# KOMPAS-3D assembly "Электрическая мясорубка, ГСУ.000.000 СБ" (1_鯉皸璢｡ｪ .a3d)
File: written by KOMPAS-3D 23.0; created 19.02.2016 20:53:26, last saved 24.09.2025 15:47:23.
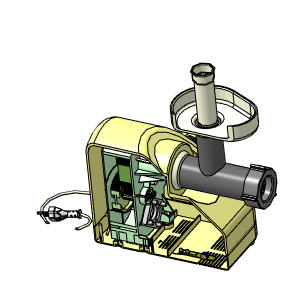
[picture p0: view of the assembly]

Document properties: Автор: Аня; Полное имя файла: C:\Users\zyrianova_ae\Desktop\Задание_колледж\Модели\Сборка мясорубки.a3d

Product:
- Component [detail]: Основание корпуса  | pos. 1  | Материал: Фторопласт-4  ГОСТ 10007-80 Е (density 2200 kg/m3); Масса: 0.272568; Автор: Аня; source file: Основание корпуса.m3d
- Component [detail]: Амортизатор  | pos. 10  | Масса: 0.016894; Автор: Аня; source file: Амортизатор (4 шт).m3d
- Component [detail]: Амортизатор  | pos. 11  | Масса: 0.016894; Автор: Аня; source file: Амортизатор (4 шт).m3d
- Component [detail]: Амортизатор  | pos. 12  | Масса: 0.016894; Автор: Аня; source file: Амортизатор (4 шт).m3d
- Component [detail]: Амортизатор  | pos. 13  | Масса: 0.016894; Автор: Аня; source file: Амортизатор (4 шт).m3d
- Component [detail]: Подушечка  | pos. 14  | Масса: 0.003215; Автор: Аня; source file: Подушечка .m3d
- Component [detail]: Подушечка  | pos. 15  | Масса: 0.003215; Автор: Аня; source file: Подушечка .m3d
- Component [detail]: Подушечка  | pos. 16  | Масса: 0.003215; Автор: Аня; source file: Подушечка .m3d
- Component [detail]: Подушечка  | pos. 17  | Масса: 0.003215; Автор: Аня; source file: Подушечка .m3d
- Component [detail]: Подушечка  | pos. 18  | Масса: 0.003215; Автор: Аня; source file: Подушечка .m3d
- Component [detail]: Подушечка  | pos. 19  | Масса: 0.003215; Автор: Аня; source file: Подушечка .m3d
- Component [detail]: Подушечка  | pos. 20  | Масса: 0.003215; Автор: Аня; source file: Подушечка .m3d
- Component [detail]: Подушечка  | pos. 21  | Масса: 0.003215; Автор: Аня; source file: Подушечка .m3d
- Component [assembly]: Редуктор  | pos. 2  | Масса: 3.0172; Автор: Аня; source file: Сборка редуктора.a3d
- Component [assembly]: Выключатель  | pos. 4  | Масса: 0.033755; Автор: Аня; source file: Выключатель.a3d
- Component [detail]: Плата  | pos. 5  | Масса: 0.019638; Автор: Аня; source file: Плата.m3d
- Component [assembly]: Сборка внешних деталей мясорубки  | pos. 6  | Масса: 5.888839; Автор: Аня; source file: Вторая сборка.a3d
- Component [detail]: Стопорный болт  | pos. 7  | Масса: 0.088582; Автор: Аня; source file: Стопорный болт.m3d
- Component [detail]: Вилка  | pos. 8  | Масса: 0.091381; Автор: Аня; source file: Вилка.m3d
- Component [detail]: Держатель провода  | pos. 9  | Масса: 0.003792; Автор: Аня; source file: Держатель провода.m3d
- Body: Тело 3
    Масса: 0.039235
- Component [standard]: Шайба A 4 ГОСТ 6958-78  | qty 4  | Масса: 0.000774; Раздел спецификации: Стандартные изделия; Рассекать на разрезах: no
- Component [standard]: Шуруп 1-4x20.019 ГОСТ 1144-80  | qty 4  | pos. 36  | Материал: Сталь 08кп ГОСТ 1050-2013 (density 7871 kg/m3); Масса: 0.00198; Раздел спецификации: Стандартные изделия; Рассекать на разрезах: no; additional columns: BOSimple***Material:aed9f2af-caf6-4059-826c-b94d4af93e47
- Part/product: Электрическая мясорубка  | designation ГСУ.000.000 СБ
    Масса: 9.559299

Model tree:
1. Сечение поверхностью:1
2. Смещенная плоскость:1
     Расстояние = 15
3. Смещенная плоскость:2
     Расстояние = 63
4. Эскиз:1
5. Эскиз:3  (with: Операция выдавливания:2)
6. Эскиз:4  (with: Операция выдавливания:6)
7. Эскиз:6  (with: Операция выдавливания:2, Вырезать элемент выдавливания:14)
8. Эскиз:7  (with: Вырезать элемент выдавливания:1, Вырезать элемент выдавливания:2)
9. Смещенная плоскость:3  (with: Операция выдавливания:2)
     Расстояние = 12
10. Эскиз:8  (with: Операция выдавливания:1)
11. Эскиз:9  (with: Операция выдавливания:6, Вырезать элемент выдавливания:14)
12. Эскиз:10  (with: Операция выдавливания:2, Вырезать элемент выдавливания:14)
13. Эскиз:11  (with: Операция выдавливания:2)
14. Эскиз:12  (with: Операция выдавливания:7)
15. Эскиз:13  (with: Операция выдавливания:1, Вырезать элемент выдавливания:20)
16. Сплайн:4
     Координата X = 24.0569; Координата Y = 47.5876; Координата Z = 4.9171; Координата X = -2.76426; Координата Y = 55.0577; Координата Z = 3.36768; Координата X = -16.3145; Координата Y = 63.0116; Координата Z = 3; Координата X = -38.7823; Координата Y = 63; Координата Z = 2.99512; Координата X = -61.2823; Координата Y = 63; Координата Z = 2.99512; Координата X = -82; Координата Y = 30.4165; Координата Z = -3.17361; Координата X = -100; Координата Z = -10; Координата X = -102; Координата Z = -10; Координата X = -120.657; Координата Y = -31.7341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
17. Кинематическая операция:3
18. Эскиз:14  (with: Кинематическая операция:3)
19. Эскиз:15  (with: Операция выдавливания:2)
20. Смещенная плоскость:5  (with: Вырезать элемент выдавливания:1)
     Расстояние = 3
21. Эскиз:16
22. Эскиз:17  (with: Кинематическая операция:3)
23. Смещенная плоскость:6  (with: Операция выдавливания:1)
     Расстояние = 2
24. Эскиз:20
25. Сплайн:7
     Координата X = 24.0569; Координата Y = 46.8619; Координата Z = 4.87679; Координата X = 24.0569; Координата Y = 38.923; Координата Z = -0.744157; Координата X = 9.1117; Координата Y = 32; Координата Z = -6.60744; Порядок = 4
26. Кинематическая операция:7
27. Эскиз:21  (with: Операция выдавливания:1)
28. Эскиз:22  (with: Кинематическая операция:3)
29. Смещенная плоскость:7  (with: Операция выдавливания:2)
     Расстояние = 2
30. Смещенная плоскость:8  (with: Вырезать элемент выдавливания:1)
     Расстояние = 7
31. Эскиз:24
32. Эскиз:26
33. Сплайн:9
     Координата X = 24.0569; Координата Y = 48.3019; Координата Z = 4.84943; Координата X = 34.1389; Координата Y = 35.7895; Координата Z = 8; Координата X = 50.0249; Координата Y = 30.353; Координата Z = 8; Координата X = 53.724; Координата Y = 30.4898; Координата Z = 4; Координата X = 46.724; Координата Y = 30.4898; Координата Z = 4; Порядок = 4
34. Эскиз:27  (with: Кинематическая операция:3)
35. Кинематическая операция:9
36. Смещенная плоскость:9  (with: Операция выдавливания:1)
     Расстояние = 2
37. Эскиз:28  (with: Вырезать элемент выдавливания:1)
38. Эскиз:30  (with: Операция выдавливания:1)
39. Эскиз:33  (with: Операция выдавливания:1)
40. Смещенная плоскость:10  (with: Вырезать элемент выдавливания:1)
     Расстояние = 5
41. Эскиз:34
42. Смещенная плоскость:11  (with: Вырезать элемент выдавливания:1)
     Расстояние = 6
43. Эскиз:35  (with: Вырезать элемент выдавливания:1)
44. Смещенная плоскость:12  (with: Операция выдавливания:2)
     Расстояние = 6
45. Эскиз:36  (with: Скругление:1)
46. Смещенная плоскость:13  (with: Вырезать элемент выдавливания:1)
     Расстояние = 6
47. Эскиз:39  (with: Вырезать элемент выдавливания:1, Скругление:5)
48. Эскиз:40  (with: Операция выдавливания:1)
49. Смещенная плоскость:15  (with: Операция выдавливания:1)
     Расстояние = 32
50. Смещенная плоскость:16  (with: Вырезать элемент выдавливания:1)
     Расстояние = 41
51. Смещенная плоскость:24  (with: Операция выдавливания:1)
     Расстояние = 1.5
52. Эскиз:60
53. Эскиз:67
54. Смещенная плоскость:26  (with: Операция выдавливания:1)
     Расстояние = 2
55. Эскиз:68
56. Эскиз:69  (with: Операция выдавливания:1)
57. Эскиз:72  (with: Операция выдавливания:1, Вырезать элемент выдавливания:1)
     Расстояние = 1.3; Ориентация = 2; Расстояние = 2

Referenced files in C:\Users\zyrianova_ae\Desktop\Задание_колледж\Модели\: основание корпуса.m3d, Амортизатор (4 шт).m3d, Подушечка .m3d, Сборка редуктора.a3d, Выключатель.a3d, Плата.m3d, Вторая сборка.a3d, Стопорный болт.m3d, Вилка.m3d, Держатель провода.m3d
Referenced files in C:\DB\SI\Methods\Kompas\3D\: PLib_Washer_1_712.m3d, PLib_Screw_Shurup_900.m3d
Referenced files in T:\ОИТОД\Электрическая мясорубка\Электрическая мясорубка\: Амортизатор (4 шт).m3d, Подушечка .m3d
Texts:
  Крепежное изделие ГОСТ
  BOSimple***PART:9cab8f69-1b85-68b4-05a8-15578942df64***SHORTLOC:Root±140±10±10±60±10±20[Нет;Без покрытия;Без указания материала;-;4]
  BOSimple***PART:990cabac-cbed-c4a6-76a4-a34520e752f7***SHORTLOC:A86A9_907A25C3CFA14727[9;Цинковое, хроматированное;4;20;Сталь 08кп ГОСТ 1050-2013]
  BOSimple***Material:aed9f2af-caf6-4059-826c-b94d4af93e47
  ГСУ.000.000 СБ
  Точка начала. Х
  Точка начала. Y
  Точка начала. Z
  Амортизатор (1)
  Амортизатор (2)
  Амортизатор (3)
  Амортизатор (4)
  Подушечка (1)
  Подушечка (2)
  Подушечка (3)
  Подушечка (4)
  Подушечка (5)
  Подушечка (6)
  Подушечка (7)
  Подушечка (8)
  Шайба A 4 ГОСТ 6958-78 (1)
  Шайба A 4 ГОСТ 6958-78 (2)
  Шайба A 4 ГОСТ 6958-78 (3)
  Шайба A 4 ГОСТ 6958-78 (4)
  Шуруп 1-4x20.019 ГОСТ 1144-80 (1)
  head2
  head4
  groove1
  fillet4
  head3
  groove4
  head5
  fillet1
  groove2
  groove3
  fillet2
  groove5
  head1
  Шуруп 1-4x20.019 ГОСТ 1144-80 (2)
  Шуруп 1-4x20.019 ГОСТ 1144-80 (3)
  Шуруп 1-4x20.019 ГОСТ 1144-80 (4)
